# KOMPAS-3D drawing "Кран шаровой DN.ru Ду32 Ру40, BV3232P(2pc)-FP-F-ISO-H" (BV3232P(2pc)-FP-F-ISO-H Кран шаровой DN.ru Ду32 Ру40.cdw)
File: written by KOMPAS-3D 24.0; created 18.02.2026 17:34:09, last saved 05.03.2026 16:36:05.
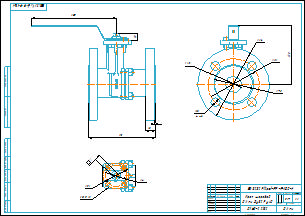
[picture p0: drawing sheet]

Document properties: Автор: R2D2; Форматы листов документа: A2; Полное имя файла: BV3232P(2pc)-FP-F-ISO-H Кран шаровой DN.ru Ду32 Ру40.m3d; Масса: 5.17; Наименование: Кран шаровой DN.ru Ду32 Ру40; Количество листов документа: 1; Примечание: D160-22132

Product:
- Part/product: Кран шаровой DN.ru Ду32 Ру40  | designation BV3232P(2pc)-FP-F-ISO-H
    Масса: 5.17
    Раздел спецификации: Прочие изделия
    Примечание: D160-22132

Views: Вид 1, Справа, Проекционный вид 2
Referenced files in E:\Работа\Зайцев\BV3232P(2pc)-FP-F-ISO-H Кран шаровой DN.ru Ду15-300 Ру16-40\DN32\: BV3232P(2pc)-FP-F-ISO-H Кран шаровой DN.ru Ду32 Ру40.m3d
Referenced files in E:\Работа\Зайцев\Для компаса\: чертеж DN.ru А3.cdt
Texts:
  BV3232P(2pc)-FP-F-ISO-H
  чертеж DN.ru А3.cdt
  Кран шаровой
  DN.ru Ду32 Ру40
  Кран шаровой DN.ru Ду32 Ру40
  BV3232P(2pc)-FP-F-ISO-H Кран шаровой DN.ru Ду32 Ру40
Dimensions and other numbers on the sheet: 0; 3; 2; 4; 15; 18; 130; 165; 115; 140; 100; 78; 4 отв.; 32; 1:1; 1; 5,17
